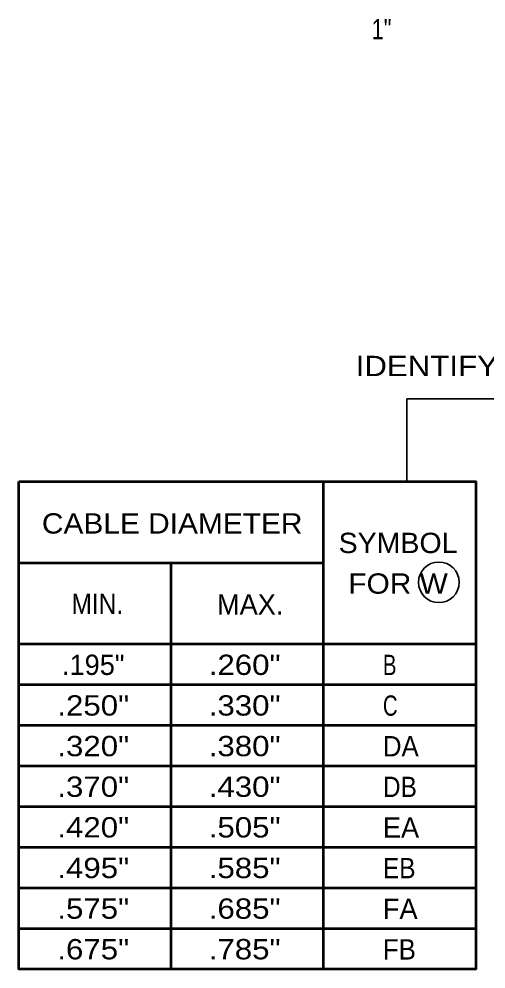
# Model space of a CAD drawing. Extents: x -1 to 679, y 0 to 440.
# Drawn here: x 242.2 to 288.2, y 245.4 to 338.9 of the extents above; entities that cross this region are included whole.
import ezdxf
from ezdxf.enums import TextEntityAlignment as Align

# ---------------------------------------------------------------- set-up
doc = ezdxf.new("R2010")
doc.units = 0
doc.header["$LTSCALE"] = 0.8
doc.layers.add('1', color=7, linetype='Continuous', lineweight=53)

msp = doc.modelspace()

# ---------------------------------------------------------------- linework, layer by layer
at = {"layer": '1', "lineweight": 35}
for p, q in [((318.4045, 301.5149), (280.4045, 301.5149)), ((280.4045, 301.5149), (280.4045, 293.5149))]:
    msp.add_line(p, q, dxfattribs=at)
at = {"layer": '1'}
for p, q in [((272.2067, 245.3847), (272.2067, 293.3847)), ((242.2067, 285.3847), (272.2067, 285.3847)), ((257.2067, 245.3847), (257.2067, 285.3847)), ((242.2067, 277.3847), (287.2067, 277.3847)), ((242.2067, 273.3847), (287.2067, 273.3847)), ((242.2067, 269.3847), (287.2067, 269.3847)), ((242.2067, 265.3847), (287.2067, 265.3847)), ((242.2067, 261.3847), (287.2067, 261.3847)), ((242.2067, 257.3847), (287.2067, 257.3847)), ((242.2067, 253.3847), (287.2067, 253.3847)), ((242.2067, 249.3847), (287.2067, 249.3847))]:
    msp.add_line(p, q, dxfattribs=at)
msp.add_lwpolyline([(242.2067, 293.3847), (287.2067, 293.3847), (287.2067, 245.3847), (242.2067, 245.3847)], close=True, dxfattribs=at)
at = {"layer": '1', "lineweight": 35}
msp.add_circle((283.5637, 283.4516), 2, dxfattribs=at)

# ---------------------------------------------------------------- texts
at = {"layer": '1'}
for s, width, p in [('1"', 0.8, (276.9471, 336.9118)), ('IDENTIFYING SYMBOLS II -', 1.15, (275.3712, 303.7543)), ('CABLE DIAMETER', 1.1, (244.4642, 288.2515)), ('MIN.', 0.9, (247.382, 280.3383)), ('B', 0.75, (278.0521, 274.3168)), ('C', 0.75, (278.0521, 270.3168)), ('DA', 0.95, (278.0521, 266.3168)), ('DB', 0.9, (278.0521, 262.3168)), ('EB', 0.9, (278.0521, 254.3167)), ('FB', 0.95, (278.0521, 246.3167))]:
    msp.add_text(s, height=2, dxfattribs=dict(at, width=width)).set_placement(p)
for s, width, p in [('SYMBOL', 1.05, (279.5435, 286.3327)), ('FOR W', 1.1, (279.5434, 282.3327)), ('.260"', 1.15, (264.4353, 274.3335)), ('.250"', 1.15, (249.5217, 270.3335)), ('.330"', 1.15, (264.4353, 270.3335)), ('.320"', 1.15, (249.5217, 266.3335)), ('.380"', 1.15, (264.4353, 266.3335)), ('.370"', 1.15, (249.5217, 262.3335)), ('.430"', 1.15, (264.4353, 262.3335)), ('.420"', 1.15, (249.5217, 258.3335)), ('.505"', 1.15, (264.4353, 258.3335)), ('.495"', 1.15, (249.5217, 254.3335)), ('.585"', 1.15, (264.4353, 254.3335)), ('.575"', 1.15, (249.5217, 250.3335)), ('.685"', 1.15, (264.4353, 250.3335)), ('.675"', 1.15, (249.5217, 246.3335)), ('.785"', 1.15, (264.4353, 246.3335))]:
    msp.add_text(s, height=2, dxfattribs=dict(at, width=width)).set_placement(p, align=Align.CENTER)
for s, p in [('MAX.', (261.712, 280.2734)), ('EA', (278.0521, 258.3168)), ('FA', (278.0521, 250.3167))]:
    msp.add_text(s, height=2, dxfattribs=at).set_placement(p)
msp.add_text('.195"', height=2, dxfattribs=at).set_placement((249.5218, 274.3335), align=Align.CENTER)

doc.saveas('drawing.dxf')
